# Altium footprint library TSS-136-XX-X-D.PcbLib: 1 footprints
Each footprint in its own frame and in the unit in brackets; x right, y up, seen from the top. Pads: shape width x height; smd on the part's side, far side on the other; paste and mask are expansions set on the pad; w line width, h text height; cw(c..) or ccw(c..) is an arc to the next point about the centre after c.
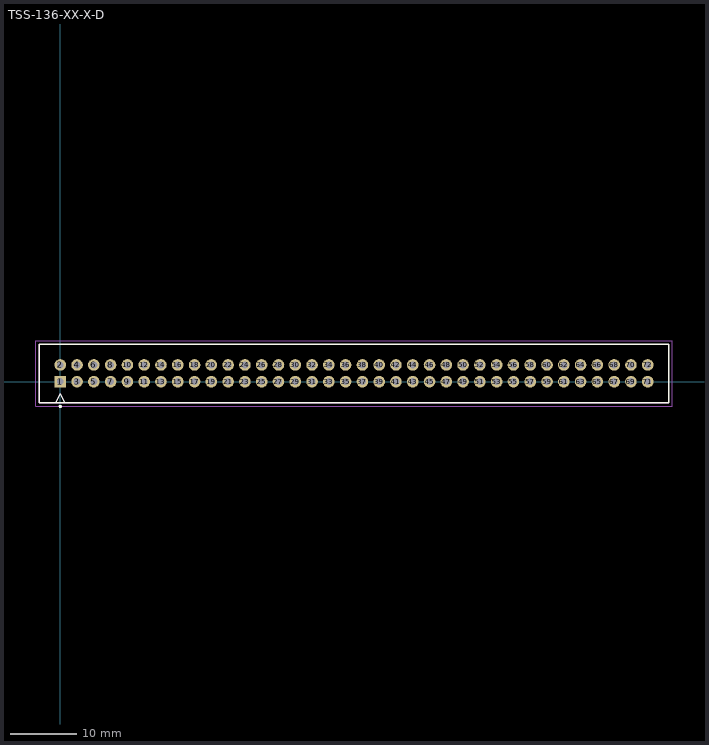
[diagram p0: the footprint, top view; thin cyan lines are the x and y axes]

## TSS-136-XX-X-D [mm] "2.54mm pitch, 72 pin, header; shrouded"
height 8.89
pads (72):
  rect 1.75x1.75 / inner round 1.75 / far side rect 1.75x1.75 hole 1.05 mask+0: 1(0,0)
  round 1.75 hole 1.05 mask+0: 2(0,2.54) 3(2.54,0) 4(2.54,2.54) 5(5.08,0) 6(5.08,2.54) 7(7.62,0) 8(7.62,2.54) 9(10.16,0) 10(10.16,2.54) 11(12.7,0) 12(12.7,2.54) 13(15.24,0) 14(15.24,2.54) 15(17.78,0) 16(17.78,2.54) 17(20.32,0) 18(20.32,2.54) 19(22.86,0) 20(22.86,2.54) 21(25.4,0) 22(25.4,2.54) 23(27.94,0) 24(27.94,2.54) 25(30.48,0) 26(30.48,2.54) 27(33.02,0) 28(33.02,2.54) 29(35.56,0) 30(35.56,2.54) 31(38.1,0) 32(38.1,2.54) 33(40.64,0) 34(40.64,2.54) 35(43.18,0) 36(43.18,2.54) 37(45.72,0) 38(45.72,2.54) 39(48.26,0) 40(48.26,2.54) 41(50.8,0) 42(50.8,2.54) 43(53.34,0) 44(53.34,2.54) 45(55.88,0) 46(55.88,2.54) 47(58.42,0) 48(58.42,2.54) 49(60.96,0) 50(60.96,2.54) 51(63.5,0) 52(63.5,2.54) 53(66.04,0) 54(66.04,2.54) 55(68.58,0) 56(68.58,2.54) 57(71.12,0) 58(71.12,2.54) 59(73.66,0) 60(73.66,2.54) 61(76.2,0) 62(76.2,2.54) 63(78.74,0) 64(78.74,2.54) 65(81.28,0) 66(81.28,2.54) 67(83.82,0) 68(83.82,2.54) 69(86.36,0) 70(86.36,2.54) 71(88.9,0) 72(88.9,2.54)
Top Overlay:
  circle w0.25: c0,-3.75 r0.125
  lines w0.2: -3.2,-3.2 -3.2,5.7 92.1,5.7 92.1,-3.2 -3.2,-3.2 ; -0.646,-3.2 0.646,-3.2 0,-1.8 -0.646,-3.2
Mechanical 12:
  lines w0.001: -3.2,-3.2 -3.2,5.7 92.1,5.7 92.1,-3.2 -3.2,-3.2
Mechanical 13:
  lines w0.1: -3.2,-3.2 -3.2,5.7 92.1,5.7 92.1,-3.2 -3.2,-3.2 ; -0.646,-3.2 0.646,-3.2 0,-1.8 -0.646,-3.2
  text ".Designator" at 0,0 h1.52
Mechanical 15:
  lines w0.05: -3.7,-3.7 -3.7,6.2 92.6,6.2 92.6,-3.7 -3.7,-3.7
